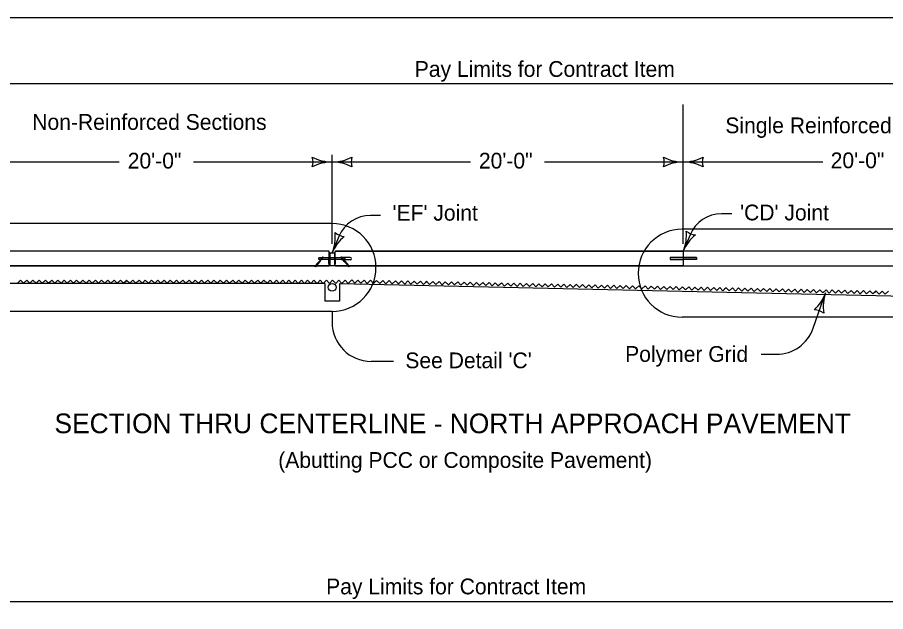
# Model space of a CAD drawing. Extents: x 10130 to 81668, y 5440 to 21644.
# Drawn here: x 14614 to 15496, y 9341 to 9944 of the extents above; entities that cross this region are included whole.
import ezdxf

# ---------------------------------------------------------------- set-up
doc = ezdxf.new("R2010")
doc.units = 0
for name, color, linetype in [('dsnNonPlotable', 7, 'Continuous'), ('dsnStdBlock', 7, 'Continuous'), ('dsnStdBlockModified', 7, 'Continuous'), ('dsnStdBlockNotModified', 7, 'Continuous'), ('dsnStdBorder', 7, 'Continuous'), ('SheetBorder', 7, 'Continuous')]:
    doc.layers.add(name, color=color, linetype=linetype)

msp = doc.modelspace()

# ---------------------------------------------------------------- linework, layer by layer
at = {"layer": 'dsnNonPlotable'}
for p, q in [((16092.07, 9876.46), (14220.97, 9876.46)), ((15290.17, 9714.12), (15290.17, 9855.76)), ((14933.77, 9714.12), (14933.77, 9804.69)), ((14717.7, 9797.26), (14577.37, 9797.26)), ((14933.77, 9797.26), (14792.98, 9797.26)), ((15074.1, 9797.26), (14933.77, 9797.26)), ((15290.17, 9797.26), (15149.38, 9797.26)), ((15431.88, 9797.26), (15290.17, 9797.26)), ((14129.3, 9351.39), (16000.4, 9351.39))]:
    msp.add_line(p, q, dxfattribs=at)
for centre, radius, start, end in [((14897.93, 9797.26), 16.51, 342.26665, 17.73335), ((14933.77, 9840.01), 42.75, 241.92751, 270), ((14897.93, 9797.26), 16.51, 342.26665, 17.73335), ((14933.77, 9840.01), 42.75, 241.92751, 270), ((14933.77, 9840.01), 42.75, 270, 298.07249), ((14969.61, 9797.26), 16.51, 162.26665, 197.73335), ((15254.33, 9797.26), 16.51, 342.26665, 17.73335), ((15290.17, 9840.01), 42.75, 241.92751, 270), ((15290.17, 9840.01), 42.75, 270, 298.07249), ((15326.01, 9797.26), 16.51, 162.26665, 197.73335), ((14933.77, 9754.51), 42.75, 90, 118.07249), ((14933.77, 9754.51), 42.75, 90, 118.07249), ((14933.77, 9754.51), 42.75, 61.92751, 90), ((15290.17, 9754.51), 42.75, 90, 118.07249), ((15290.17, 9754.51), 42.75, 61.92751, 90)]:
    msp.add_arc(centre, radius, start, end, dxfattribs=at)
at = {"layer": 'dsnStdBlock'}
for p, q in [((14931.39, 9705.1), (14930.8, 9705.1)), ((14936.74, 9705.1), (14936.15, 9705.1))]:
    msp.add_line(p, q, dxfattribs=at)
for points in [[(14936.15, 9705.05), (14936.1, 9705.1)], [(14647.58, 9675.82), (14646, 9674.23), (14642.83, 9677.41), (14639.66, 9674.24), (14636.49, 9677.41), (14633.33, 9674.24), (14630.16, 9677.41), (14626.99, 9674.24), (14623.82, 9677.41), (14620.65, 9674.25), (14617.49, 9677.41), (14614.32, 9674.25)], [(14723.61, 9675.79), (14722.03, 9674.21), (14718.86, 9677.38), (14715.69, 9674.21), (14712.53, 9677.38), (14709.36, 9674.21), (14706.19, 9677.38), (14703.02, 9674.21), (14699.85, 9677.38), (14696.69, 9674.22), (14693.52, 9677.39), (14690.35, 9674.22), (14687.18, 9677.39), (14684.01, 9674.22), (14680.85, 9677.39), (14677.68, 9674.23), (14674.51, 9677.39), (14671.34, 9674.23), (14668.17, 9677.39), (14665.01, 9674.23), (14661.84, 9677.4), (14658.67, 9674.23), (14655.5, 9677.4), (14652.33, 9674.23), (14649.17, 9677.4), (14647.58, 9675.82)], [(14799.65, 9675.76), (14798.06, 9674.18), (14794.89, 9677.35), (14791.73, 9674.18), (14788.56, 9677.35), (14785.39, 9674.18), (14782.22, 9677.35), (14779.05, 9674.19), (14775.89, 9677.35), (14772.72, 9674.19), (14769.55, 9677.36), (14766.38, 9674.19), (14763.21, 9677.36), (14760.05, 9674.19), (14756.88, 9677.36), (14753.71, 9674.2), (14750.54, 9677.37), (14747.37, 9674.2), (14744.21, 9677.37), (14741.04, 9674.2), (14737.87, 9677.37), (14734.7, 9674.21), (14731.53, 9677.37), (14728.37, 9674.21), (14725.2, 9677.37), (14723.61, 9675.79)], [(14875.68, 9675.73), (14874.09, 9674.15), (14870.93, 9677.32), (14867.76, 9674.16), (14864.59, 9677.32), (14861.42, 9674.16), (14858.25, 9677.32), (14855.09, 9674.16), (14851.92, 9677.33), (14848.75, 9674.16), (14845.58, 9677.33), (14842.41, 9674.16), (14839.25, 9677.33), (14836.08, 9674.17), (14832.91, 9677.33), (14829.74, 9674.17), (14826.57, 9677.34), (14823.41, 9674.17), (14820.24, 9677.34), (14817.07, 9674.17), (14813.9, 9677.34), (14810.73, 9674.18), (14807.57, 9677.35), (14804.4, 9674.18), (14801.23, 9677.35), (14799.65, 9675.76)], [(14951.71, 9675.71), (14950.13, 9674.12), (14946.96, 9677.3), (14943.79, 9674.13), (14940.62, 9677.3), (14937.45, 9674.13), (14934.29, 9677.3), (14931.12, 9674.13), (14927.95, 9677.3), (14924.78, 9674.13), (14921.61, 9677.3), (14918.45, 9674.13), (14915.28, 9677.3), (14912.11, 9674.14), (14908.94, 9677.31), (14905.77, 9674.14), (14902.61, 9677.31), (14899.44, 9674.14), (14896.27, 9677.31), (14893.1, 9674.14), (14889.93, 9677.32), (14886.77, 9674.15), (14883.6, 9677.32), (14880.43, 9674.15), (14877.26, 9677.32), (14875.68, 9675.73)], [(15028.06, 9674.7), (15026.44, 9673.14), (15023.33, 9676.36), (15020.11, 9673.25), (15017, 9676.48), (15013.77, 9673.36), (15010.66, 9676.59), (15007.44, 9673.47), (15004.33, 9676.7), (15001.1, 9673.58), (14997.99, 9676.81), (14994.77, 9673.69), (14991.66, 9676.92), (14988.43, 9673.8), (14985.32, 9677.03), (14982.1, 9673.92), (14978.99, 9677.14), (14975.76, 9674.02), (14972.65, 9677.25), (14969.43, 9674.14), (14966.32, 9677.36), (14963.09, 9674.25), (14959.98, 9677.47), (14956.76, 9674.35), (14953.65, 9677.58), (14951.71, 9675.71)], [(15104.07, 9673.07), (15102.46, 9671.52), (15099.35, 9674.76), (15096.12, 9671.66), (15093.02, 9674.89), (15089.79, 9671.8), (15086.69, 9675.03), (15083.45, 9671.93), (15080.35, 9675.16), (15077.12, 9672.06), (15074.02, 9675.3), (15070.79, 9672.2), (15067.68, 9675.44), (15064.45, 9672.33), (15061.35, 9675.57), (15058.11, 9672.47), (15055.01, 9675.71), (15051.78, 9672.61), (15048.68, 9675.84), (15045.44, 9672.74), (15042.35, 9675.98), (15039.11, 9672.88), (15036.01, 9676.11), (15032.78, 9673.02), (15029.67, 9676.25), (15028.06, 9674.7)], [(15180.09, 9671.45), (15178.47, 9669.9), (15175.37, 9673.13), (15172.14, 9670.03), (15169.03, 9673.27), (15165.8, 9670.17), (15162.7, 9673.4), (15159.47, 9670.3), (15156.37, 9673.54), (15153.13, 9670.44), (15150.03, 9673.67), (15146.8, 9670.58), (15143.7, 9673.81), (15140.46, 9670.71), (15137.36, 9673.94), (15134.13, 9670.85), (15131.03, 9674.08), (15127.8, 9670.98), (15124.69, 9674.22), (15121.46, 9671.11), (15118.36, 9674.35), (15115.12, 9671.25), (15112.03, 9674.49), (15108.79, 9671.39), (15105.69, 9674.62), (15104.07, 9673.07)], [(15256.1, 9669.82), (15254.48, 9668.27), (15251.39, 9671.5), (15248.15, 9668.41), (15245.05, 9671.64), (15241.82, 9668.54), (15238.71, 9671.78), (15235.48, 9668.68), (15232.38, 9671.92), (15229.15, 9668.81), (15226.05, 9672.05), (15222.81, 9668.95), (15219.71, 9672.18), (15216.48, 9669.08), (15213.38, 9672.32), (15210.14, 9669.22), (15207.04, 9672.45), (15203.81, 9669.36), (15200.71, 9672.59), (15197.47, 9669.49), (15194.37, 9672.72), (15191.14, 9669.63), (15188.04, 9672.86), (15184.8, 9669.76), (15181.71, 9673), (15180.09, 9671.45)], [(15332.11, 9668.19), (15330.5, 9666.64), (15327.4, 9669.88), (15324.16, 9666.78), (15321.07, 9670.01), (15317.83, 9666.92), (15314.73, 9670.15), (15311.5, 9667.05), (15308.39, 9670.28), (15305.16, 9667.19), (15302.06, 9670.42), (15298.83, 9667.32), (15295.73, 9670.56), (15292.49, 9667.46), (15289.39, 9670.7), (15286.16, 9667.59), (15283.06, 9670.83), (15279.82, 9667.73), (15276.72, 9670.96), (15273.49, 9667.86), (15270.39, 9671.1), (15267.16, 9668), (15264.05, 9671.23), (15260.82, 9668.14), (15257.72, 9671.37), (15256.1, 9669.82)], [(15408.13, 9666.57), (15406.52, 9665.02), (15403.41, 9668.26), (15400.18, 9665.15), (15397.08, 9668.39), (15393.84, 9665.29), (15390.75, 9668.52), (15387.51, 9665.42), (15384.41, 9668.66), (15381.18, 9665.56), (15378.07, 9668.79), (15374.84, 9665.7), (15371.74, 9668.93), (15368.51, 9665.83), (15365.41, 9669.06), (15362.17, 9665.97), (15359.07, 9669.2), (15355.84, 9666.1), (15352.74, 9669.34), (15349.5, 9666.24), (15346.4, 9669.48), (15343.17, 9666.37), (15340.07, 9669.61), (15336.84, 9666.51), (15333.73, 9669.74), (15332.11, 9668.19)], [(15484.15, 9664.94), (15482.53, 9663.39), (15479.43, 9666.62), (15476.2, 9663.53), (15473.09, 9666.76), (15469.86, 9663.66), (15466.76, 9666.9), (15463.52, 9663.8), (15460.43, 9667.04), (15457.19, 9663.93), (15454.09, 9667.17), (15450.86, 9664.07), (15447.76, 9667.3), (15444.52, 9664.2), (15441.42, 9667.44), (15438.19, 9664.34), (15435.09, 9667.57), (15431.85, 9664.48), (15428.76, 9667.71), (15425.52, 9664.61), (15422.42, 9667.84), (15419.18, 9664.75), (15416.08, 9667.98), (15412.85, 9664.88), (15409.75, 9668.12), (15408.13, 9666.57)], [(15498.43, 9666.22), (15495.2, 9663.12), (15492.1, 9666.35), (15488.86, 9663.26), (15485.76, 9666.49), (15484.15, 9664.94)]]:
    msp.add_lwpolyline(points, dxfattribs=at)
at = {"layer": 'dsnStdBlockModified'}
for p, q in [((14930.38, 9706.7), (14577.37, 9706.74)), ((14930.8, 9706.28), (14930.8, 9706.28)), ((14930.8, 9691.85), (14930.8, 9706.28)), ((15646.57, 9706.7), (15290.17, 9706.7)), ((15290.17, 9706.7), (15290.17, 9700.2)), ((15290.17, 9700.2), (15303.54, 9700.2)), ((15303.54, 9698.35), (15290.17, 9698.35)), ((15290.17, 9698.35), (15290.17, 9691.85)), ((15303.54, 9700.2), (15303.54, 9698.34)), ((14577.37, 9691.89), (14843.21, 9691.85)), ((14843.21, 9691.85), (14930.8, 9691.85)), ((15290.17, 9691.85), (15646.57, 9691.85))]:
    msp.add_line(p, q, dxfattribs=at)
msp.add_lwpolyline([(14930.8, 9706.28), (14930.71, 9706.63), (14930.38, 9706.7)], dxfattribs=at)
at = {"layer": 'dsnStdBlockNotModified'}
for p, q in [((14983.04, 9743.09), (14972.7, 9743.09)), ((15339.44, 9744.7), (15329.1, 9744.7)), ((14933.77, 9734.8), (14220.97, 9734.8)), ((16092.07, 9728.97), (15288.91, 9728.97)), ((14940.7, 9721.75), (14933.77, 9705.1)), ((15297.1, 9723.36), (15290.17, 9706.7)), ((15422.14, 9628.73), (15434.64, 9664.68)), ((14933.77, 9645.7), (14220.97, 9645.7)), ((14933.77, 9645.7), (14933.77, 9634.6)), ((16092.07, 9639.87), (15288.91, 9639.87)), ((15369.4, 9602.14), (15384.74, 9602.14)), ((14996.01, 9595), (14973.37, 9595))]:
    msp.add_line(p, q, dxfattribs=at)
for centre, radius, start, end in [((14972.69, 9708.45), 34.65, 90, 157.40929), ((15329.09, 9710.05), 34.65, 90, 157.40929), ((14933.77, 9690.25), 44.55, 270, 90), ((15288.91, 9684.42), 44.55, 90, 269.99892), ((14894.3, 9721.52), 42.75, 337.40819, 5.48068), ((14973.24, 9688.67), 42.75, 129.3357, 157.40819), ((14947.54, 9738.19), 16.51, 229.67484, 265.14154), ((15250.7, 9723.12), 42.75, 337.40819, 5.48068), ((15329.64, 9690.28), 42.75, 129.3357, 157.40819), ((15303.94, 9739.79), 16.51, 229.67484, 265.14154), ((15394.26, 9678.72), 42.75, 312.75242, 340.82491), ((15475.01, 9650.64), 42.75, 160.82491, 188.8974), ((15422.86, 9630.82), 16.51, 53.09156, 88.55826), ((14973.37, 9634.6), 39.6, 180, 270), ((15384.73, 9641.74), 39.6, 270, 340.8231)]:
    msp.add_arc(centre, radius, start, end, dxfattribs=at)
at = {"layer": 'dsnStdBorder'}
for p, q in [((14930.39, 9706.7), (14220.97, 9706.7)), ((14930.8, 9696.36), (14930.8, 9706.28)), ((14930.86, 9705.1), (14930.86, 9696.36)), ((14930.92, 9705.1), (14930.92, 9696.36)), ((14930.98, 9705.1), (14930.98, 9696.36)), ((14931.04, 9705.1), (14931.04, 9696.36)), ((14931.1, 9705.1), (14931.1, 9696.36)), ((14931.16, 9705.1), (14931.16, 9696.36)), ((14931.22, 9705.1), (14931.22, 9696.36)), ((14931.28, 9705.1), (14931.28, 9696.36)), ((14931.34, 9705.1), (14931.34, 9696.36)), ((14931.39, 9705.1), (14931.39, 9700.17)), ((14931.39, 9705.1), (14936.15, 9705.1)), ((14931.39, 9700.17), (14931.39, 9705.1)), ((14936.15, 9705.1), (14936.15, 9700.17)), ((14936.15, 9705.1), (14936.15, 9700.17)), ((14936.21, 9705.1), (14936.21, 9696.36)), ((14936.27, 9705.1), (14936.27, 9696.36)), ((14936.33, 9705.1), (14936.33, 9696.36)), ((14936.38, 9705.1), (14936.38, 9696.36)), ((14936.45, 9705.1), (14936.45, 9696.36)), ((14936.5, 9705.1), (14936.5, 9696.36)), ((14936.57, 9705.1), (14936.57, 9696.36)), ((14936.62, 9705.1), (14936.62, 9696.36)), ((14936.69, 9705.1), (14936.69, 9696.36)), ((14936.74, 9696.36), (14936.74, 9706.28)), ((14936.75, 9700.18), (14936.75, 9706.28)), ((14937.16, 9706.7), (15290.18, 9706.7)), ((16092.07, 9706.7), (14937.16, 9706.7)), ((15290.17, 9706.7), (15290.17, 9691.85)), ((15290.18, 9706.7), (15290.18, 9700.2)), ((14918.73, 9694.27), (14916.31, 9691.4)), ((14919.66, 9694.27), (14916.86, 9690.94)), ((14920.48, 9696.36), (14918.73, 9694.27)), ((14921.42, 9696.36), (14919.66, 9694.27)), ((14920.41, 9698.38), (14920.41, 9700.17)), ((14923.67, 9700.17), (14920.41, 9700.17)), ((14922.18, 9698.38), (14920.41, 9698.38)), ((14924.16, 9700.75), (14920.48, 9696.36)), ((14921.42, 9696.36), (14924.71, 9700.29)), ((14930.44, 9698.38), (14923.11, 9698.38)), ((14923.67, 9700.17), (14923.67, 9700.17)), ((14930.44, 9700.17), (14924.61, 9700.17)), ((14930.44, 9694.23), (14930.44, 9700.17)), ((14930.44, 9699.93), (14930.44, 9699.93)), ((14930.8, 9694.27), (14930.8, 9696.36)), ((14930.8, 9691.85), (14930.8, 9694.27)), ((14930.86, 9696.36), (14930.86, 9694.27)), ((14930.86, 9694.27), (14930.86, 9691.85)), ((14930.92, 9696.36), (14930.92, 9694.27)), ((14930.92, 9694.27), (14930.92, 9691.85)), ((14930.98, 9696.36), (14930.98, 9694.27)), ((14930.98, 9694.27), (14930.98, 9691.85)), ((14931.04, 9696.36), (14931.04, 9694.27)), ((14931.04, 9694.27), (14931.04, 9691.85)), ((14931.1, 9696.36), (14931.1, 9694.27)), ((14931.1, 9694.27), (14931.1, 9691.85)), ((14931.16, 9696.36), (14931.16, 9694.27)), ((14931.16, 9694.27), (14931.16, 9691.85)), ((14931.22, 9696.36), (14931.22, 9694.27)), ((14931.22, 9694.27), (14931.22, 9691.85)), ((14931.28, 9696.36), (14931.28, 9694.27)), ((14931.28, 9694.27), (14931.28, 9691.85)), ((14931.34, 9696.36), (14931.34, 9694.27)), ((14931.34, 9694.27), (14931.34, 9691.85)), ((14931.39, 9700.17), (14931.39, 9698.38)), ((14936.15, 9700.17), (14931.39, 9700.17)), ((14931.39, 9698.38), (14931.39, 9696.36)), ((14936.15, 9698.38), (14931.39, 9698.38)), ((14931.39, 9696.36), (14931.39, 9694.27)), ((14931.39, 9694.27), (14931.39, 9691.85)), ((14936.15, 9700.17), (14936.15, 9698.38)), ((14936.15, 9698.38), (14936.15, 9696.36)), ((14936.15, 9696.36), (14936.15, 9694.27)), ((14936.15, 9694.27), (14936.15, 9691.85)), ((14936.21, 9696.36), (14936.21, 9694.27)), ((14936.21, 9694.27), (14936.21, 9691.85)), ((14936.27, 9696.36), (14936.27, 9694.27)), ((14936.27, 9694.27), (14936.27, 9691.85)), ((14936.33, 9696.36), (14936.33, 9694.27)), ((14936.33, 9694.27), (14936.33, 9691.85)), ((14936.38, 9696.36), (14936.38, 9694.27)), ((14936.38, 9694.27), (14936.38, 9691.85)), ((14936.45, 9696.36), (14936.45, 9694.27)), ((14936.45, 9694.27), (14936.45, 9691.85)), ((14936.5, 9696.36), (14936.5, 9694.27)), ((14936.5, 9694.27), (14936.5, 9691.85)), ((14936.57, 9696.36), (14936.57, 9694.27)), ((14936.57, 9694.27), (14936.57, 9691.85)), ((14936.62, 9696.36), (14936.62, 9694.27)), ((14936.62, 9694.27), (14936.62, 9691.85)), ((14936.69, 9696.36), (14936.69, 9694.27)), ((14936.69, 9694.27), (14936.69, 9691.85)), ((14936.74, 9694.27), (14936.74, 9696.36)), ((14936.74, 9691.85), (14936.74, 9694.27)), ((14936.75, 9691.85), (14936.75, 9694.23)), ((14936.92, 9700.34), (14936.92, 9700.34)), ((14937.1, 9694.23), (14937.1, 9700.17)), ((14937.1, 9694.23), (14937.1, 9700.17)), ((14942.94, 9700.17), (14937.1, 9700.17)), ((14944.43, 9698.38), (14937.1, 9698.38)), ((14937.1, 9694.23), (14937.1, 9694.23)), ((14946.13, 9696.36), (14942.83, 9700.29)), ((14943.27, 9698.38), (14943.27, 9698.09)), ((14944.68, 9698.09), (14943.27, 9698.09)), ((14943.38, 9700.75), (14947.06, 9696.36)), ((14952.18, 9700.46), (14943.62, 9700.46)), ((14943.87, 9700.17), (14943.87, 9700.17)), ((14947.14, 9700.17), (14943.87, 9700.17)), ((14947.14, 9698.38), (14945.37, 9698.38)), ((14952.18, 9698.09), (14945.62, 9698.09)), ((14946.13, 9696.36), (14947.88, 9694.27)), ((14947.06, 9696.36), (14948.81, 9694.27)), ((14947.14, 9698.38), (14947.14, 9700.17)), ((14947.88, 9694.27), (14950.68, 9690.94)), ((14948.81, 9694.27), (14951.23, 9691.4)), ((15303.54, 9700.2), (15276.81, 9700.2)), ((15276.81, 9700.2), (15276.81, 9698.34)), ((15303.54, 9698.34), (15276.81, 9698.34)), ((15290.18, 9700.2), (15276.82, 9700.2)), ((15276.82, 9700.2), (15276.82, 9698.34)), ((15276.82, 9698.34), (15290.18, 9698.34)), ((15290.18, 9698.34), (15290.18, 9691.85)), ((15303.54, 9700.2), (15303.54, 9698.34)), ((14931.39, 9691.85), (14220.97, 9691.85)), ((14916.86, 9690.94), (14916.31, 9691.4)), ((14936.15, 9691.85), (14931.39, 9691.85)), ((14936.74, 9691.85), (14949.92, 9691.85)), ((14950.85, 9691.85), (14936.75, 9691.85)), ((14950.68, 9690.94), (14951.23, 9691.4)), ((15290.18, 9691.85), (14950.85, 9691.85)), ((14950.85, 9691.85), (15751.23, 9691.85)), ((14926.35, 9674.03), (14220.97, 9674.03)), ((14926.35, 9674.03), (14926.35, 9656.21)), ((14941.2, 9674.03), (16058.43, 9648.78)), ((14941.2, 9674.03), (14941.2, 9656.21)), ((14941.2, 9656.21), (14926.35, 9656.21))]:
    msp.add_line(p, q, dxfattribs=at)
for points in [[(15290.18, 9706.7), (15290.18, 9706.7)], [(14936.15, 9698.28), (14936.05, 9698.38)]]:
    msp.add_lwpolyline(points, dxfattribs=at)
for centre, radius in [((14921.67, 9698.15), 0.238), ((14946.12, 9697.85), 0.238), ((14916.58, 9692.09), 0.238), ((14950.96, 9692.09), 0.238), ((14933.77, 9670.07), 3.96)]:
    msp.add_circle(centre, radius, dxfattribs=at)
for centre, radius, start, end in [((14930.38, 9706.28), 0.416, 0, 90), ((14937.16, 9706.28), 0.416, 90, 180), ((14937.16, 9706.28), 0.416, 90, 180), ((14924.44, 9700.52), 0.356, 320.00367, 139.99636), ((14930.62, 9700.17), 0.178, 0, 180), ((14930.62, 9694.23), 0.178, 180, 0), ((14936.92, 9700.17), 0.178, 0, 180), ((14936.92, 9694.23), 0.178, 180, 0), ((14936.92, 9700.17), 0.178, 0, 174.56731), ((14936.92, 9694.23), 0.178, 180.06276, 0), ((14943.1, 9700.52), 0.356, 40.00364, 219.99633), ((14952.18, 9699.27), 1.19, 270, 90)]:
    msp.add_arc(centre, radius, start, end, dxfattribs=at)
for points in [[(14930.44, 9700.05), (14930.41, 9700.04), (14930.38, 9700.05), (14930.36, 9700.05), (14930.34, 9700.05), (14930.32, 9700.04), (14930.3, 9700.05)], [(14930.44, 9699.93), (14930.41, 9699.92), (14930.38, 9699.93), (14930.36, 9699.93), (14930.34, 9699.93), (14930.32, 9699.92), (14930.3, 9699.93)], [(14930.44, 9699.81), (14930.41, 9699.8), (14930.38, 9699.81), (14930.36, 9699.81), (14930.34, 9699.81), (14930.32, 9699.8), (14930.3, 9699.81)], [(14930.44, 9699.69), (14930.41, 9699.69), (14930.38, 9699.69), (14930.36, 9699.69), (14930.34, 9699.69), (14930.32, 9699.69), (14930.3, 9699.69)], [(14930.44, 9699.57), (14930.41, 9699.57), (14930.38, 9699.57), (14930.36, 9699.57), (14930.34, 9699.57), (14930.32, 9699.57), (14930.3, 9699.57)], [(14930.44, 9699.45), (14930.41, 9699.45), (14930.38, 9699.45), (14930.36, 9699.45), (14930.34, 9699.45), (14930.32, 9699.45), (14930.3, 9699.45)], [(14930.44, 9699.33), (14930.41, 9699.33), (14930.38, 9699.33), (14930.36, 9699.33), (14930.34, 9699.33), (14930.32, 9699.33), (14930.3, 9699.33)], [(14930.44, 9699.21), (14930.41, 9699.21), (14930.38, 9699.21), (14930.36, 9699.21), (14930.34, 9699.21), (14930.32, 9699.21), (14930.3, 9699.21)], [(14930.44, 9699.1), (14930.41, 9699.09), (14930.38, 9699.1), (14930.36, 9699.1), (14930.34, 9699.1), (14930.32, 9699.09), (14930.3, 9699.1)], [(14930.44, 9698.98), (14930.41, 9698.97), (14930.38, 9698.98), (14930.36, 9698.98), (14930.34, 9698.98), (14930.32, 9698.97), (14930.3, 9698.98)], [(14930.44, 9698.86), (14930.41, 9698.85), (14930.38, 9698.86), (14930.36, 9698.86), (14930.34, 9698.86), (14930.32, 9698.85), (14930.3, 9698.86)], [(14930.44, 9698.74), (14930.41, 9698.74), (14930.38, 9698.74), (14930.36, 9698.74), (14930.34, 9698.74), (14930.32, 9698.74), (14930.3, 9698.74)], [(14930.44, 9698.62), (14930.41, 9698.62), (14930.38, 9698.62), (14930.36, 9698.62), (14930.34, 9698.62), (14930.32, 9698.62), (14930.3, 9698.62)], [(14930.44, 9698.5), (14930.41, 9698.5), (14930.38, 9698.5), (14930.36, 9698.5), (14930.34, 9698.5), (14930.32, 9698.5), (14930.3, 9698.5)]]:
    msp.add_spline(points, degree=3, dxfattribs=at)
at = {"layer": 'SheetBorder'}
msp.add_lwpolyline([(13732.52, 9944.02), (16867.53, 9944.02), (16867.53, 7924.02), (13732.52, 7924.02)], close=True, dxfattribs=at)

# ---------------------------------------------------------------- texts
at = {"layer": 'dsnNonPlotable'}
for s, p in [('Pay Limits for Contract Item', (15017.65, 9883.67)), ('Non-Reinforced Sections', (14629.43, 9829.9)), ('Single Reinforced Section', (15332.89, 9826.45)), ('20\'-0"', (14726.35, 9790.63)), ('20\'-0"', (15082.75, 9790.63)), ('20\'-0"', (15439.77, 9790.94)), ('Pay Limits for Contract Item', (14927.71, 9358.6))]:
    msp.add_text(s, height=16, dxfattribs=at).set_placement(p)
at = {"layer": 'dsnStdBlock'}
msp.add_text('(Abutting PCC or Composite Pavement)', height=16, dxfattribs=at).set_placement((14879.09, 9486.87))
at = {"layer": 'dsnStdBlockModified'}
msp.add_text('SECTION THRU CENTERLINE - NORTH APPROACH PAVEMENT', height=20, dxfattribs=at).set_placement((14652.01, 9522.06))
at = {"layer": 'dsnStdBlockNotModified'}
for s, p in [("'EF' Joint", (14995.04, 9737.75)), ("'CD' Joint", (15347.81, 9738.03)), ('Polymer Grid', (15231.17, 9594.49)), ("See Detail 'C'", (15008.1, 9587.99))]:
    msp.add_text(s, height=16, dxfattribs=at).set_placement(p)

doc.saveas('drawing.dxf')
